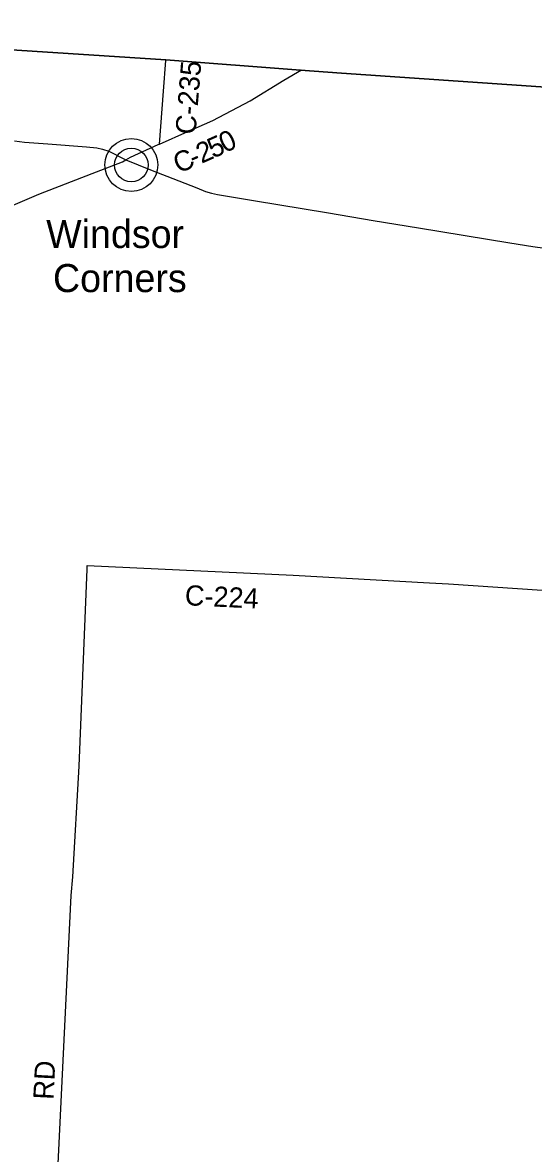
# Model space of a CAD drawing. Extents: x 1674899 to 2057726, y 653888 to 988278.
# Drawn here: x 1824392 to 1831966, y 864966 to 881757 of the extents above; entities that cross this region are included whole.
import ezdxf

# ---------------------------------------------------------------- set-up
doc = ezdxf.new("R2010")
doc.units = 0
for name, color, linetype in [('GM_X_Adjacent_County', 7, 'Continuous'), ('GM_X_County', 7, 'Continuous'), ('GM_X_County_Road', 7, 'Continuous'), ('GM_X_County_Road_Text', 7, 'Continuous'), ('GM_X_State_Route', 7, 'Continuous'), ('GM_X_Township', 7, 'Continuous'), ('GM_X_Unincorporated', 7, 'Continuous'), ('GM_X_Unincorporated_Location', 7, 'Continuous'), ('GM_X_Unincorporated_Text', 7, 'Continuous')]:
    doc.layers.add(name, color=color, linetype=linetype)

msp = doc.modelspace()

# ---------------------------------------------------------------- linework, layer by layer
at = {"layer": 'GM_X_Adjacent_County'}
msp.add_lwpolyline([(1849106, 864311), (1849634, 872258), (1850017, 877290), (1850147, 879854), (1845959, 880135), (1842150, 880416), (1839410, 880574), (1836708, 880754), (1836682, 880495), (1835395, 880574), (1829123, 881005), (1828513, 881052), (1826517, 881205), (1823082, 881429), (1823458, 886911), (1823627, 889370), (1824025, 895167), (1824431, 901093)], dxfattribs=at)
at = {"layer": 'GM_X_County'}
msp.add_lwpolyline([(1809339, 887629), (1813443, 887429), (1813717, 887422), (1814360, 887388), (1814847, 887358), (1815353, 887328), (1818316, 887169), (1823458, 886911), (1823082, 881429), (1826517, 881205), (1828513, 881052), (1829123, 881005), (1835395, 880574), (1836682, 880495), (1836708, 880754), (1839410, 880574), (1842150, 880416), (1845959, 880135), (1850147, 879854), (1850017, 877290), (1849634, 872258), (1849106, 864311)], dxfattribs=at)
at = {"layer": 'GM_X_County_Road'}
for points in [[(1826423, 879954), (1826479, 880739), (1826518, 881195)], [(1826404, 879946), (1826423, 879954), (1826844, 880138), (1827215, 880304), (1827767, 880596), (1828264, 880901), (1828526, 881056)], [(1825923, 879717), (1825991, 879759), (1826404, 879946)], [(1822822, 877662), (1822979, 877822), (1823573, 878476), (1824013, 878909), (1824059, 878945), (1824151, 879002), (1824217, 879033), (1824631, 879211), (1825422, 879515), (1825871, 879688), (1825923, 879717)], [(1824699, 860768), (1824709, 860807), (1824715, 860860), (1824883, 864100), (1825114, 868796), (1825134, 869072), (1825228, 870716), (1825347, 873642), (1825350, 873697)], [(1825350, 873697), (1828404, 873550), (1830426, 873436), (1830706, 873421), (1835899, 873073), (1835968, 873069), (1839135, 872864)]]:
    msp.add_lwpolyline(points, dxfattribs=at)
at = {"layer": 'GM_X_State_Route'}
msp.add_lwpolyline([(1824269, 880002), (1824418, 879984), (1824766, 879955), (1825340, 879913), (1825491, 879897), (1825574, 879880), (1825668, 879848), (1825923, 879717), (1826289, 879572), (1826707, 879409), (1826973, 879302), (1827103, 879251), (1827193, 879225), (1827284, 879205), (1827814, 879113), (1828926, 878930), (1829588, 878819), (1830263, 878712), (1831616, 878486), (1831957, 878431), (1832136, 878410)], dxfattribs=at)
at = {"layer": 'GM_X_Township'}
msp.add_lwpolyline([(1821956, 864281), (1822382, 871013), (1822583, 873901), (1822822, 877662), (1822932, 879384), (1823026, 880489), (1823082, 881429), (1826517, 881205), (1828513, 881052), (1829123, 881005), (1835395, 880574), (1836682, 880495), (1836708, 880754), (1839410, 880574), (1842150, 880416), (1845959, 880135), (1850147, 879854), (1850017, 877290), (1849634, 872258), (1849106, 864311)], dxfattribs=at)
at = {"layer": 'GM_X_Unincorporated'}
for radius in [393, 249]:
    msp.add_circle((1826004, 879643), radius, dxfattribs=at)
at = {"layer": 'GM_X_Unincorporated_Location'}
msp.add_line((1826004, 879643), (1826004, 879643), dxfattribs=at)

# ---------------------------------------------------------------- texts
at = {"layer": 'GM_X_County_Road_Text'}
for s, rotation, p in [('C-235', 85.3743, (1826955, 880088)), ('5', 24.1864, (1827216, 879736)), ('0', 25.9894, (1827394, 879816)), ('C', 23.544, (1826705, 879512)), ('2', 23.719, (1827045, 879660)), ('-', 23.5717, (1826931, 879611)), ('C-224', 357.2469, (1826793, 873107)), ('RD', 87.0387, (1824848, 865758))]:
    msp.add_text(s, height=300, rotation=rotation, dxfattribs=at).set_placement(p)
at = {"layer": 'GM_X_Unincorporated_Text'}
for s, p in [('Windsor', (1824741, 878410)), ('Corners', (1824842, 877755))]:
    msp.add_text(s, height=417, rotation=0, dxfattribs=at).set_placement(p)

doc.saveas('drawing.dxf')
